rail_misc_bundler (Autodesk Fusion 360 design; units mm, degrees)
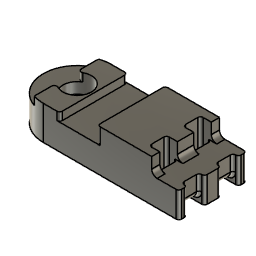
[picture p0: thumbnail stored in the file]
sketch "Sketch1" plane through (0, 0, 0) normal (0, 0, 1) x axis (1, 0, 0)
  line L1 (25, 6.25) -> (-6.25, 6.25)
  line L2 (25, -6.25) -> (25, 6.25)
  line L3 (-6.25, -6.25) -> (25, -6.25)
  line L4 (-6.25, 6.25) -> (-6.25, -6.25)
  line L5 (10, -6.25) -> (10, 6.25)
  line L6 (-2, -6.25) -> (-2, 6.25)
  line L7 (3, -6.25) -> (3, 6.25)
  line L8 (12, -6.25) -> (12, 6.25)
  line L9 (18, -4.75) -> (20, -4.75)
  line L10 (18, -1.5) -> (18, -4.75)
  line L11 (20, -1.5) -> (18, -1.5)
  line L12 (20, -4.75) -> (20, -1.5)
  line L13 (18, 1.5) -> (20, 1.5)
  line L14 (18, 4.75) -> (18, 1.5)
  line L15 (20, 4.75) -> (18, 4.75)
  line L16 (20, 1.5) -> (20, 4.75)
  line L17 (24, 4.75) -> (25, 4.75)
  line L18 (24, 1.5) -> (24, 4.75)
  line L19 (25, 1.5) -> (24, 1.5)
  line L20 (24, -1.5) -> (25, -1.5)
  line L21 (24, -4.75) -> (24, -1.5)
  line L22 (25, -4.75) -> (24, -4.75)
  line L23 (20, -1.5) -> (20, 1.5)
  line L24 (20, 6.25) -> (20, 4.75)
  line L25 (20, -6.25) -> (20, -4.75)
  line L26 (24, 4.75) -> (20, 4.75)
  line L27 (20, 1.5) -> (24, 1.5)
  line L28 (24, -1.5) -> (20, -1.5)
  line L29 (20, -4.75) -> (24, -4.75)
  circle C1 centre (0, 0) radius 2.625
  point P1 (0, 0)
  point P2 (0, 0)
  point P7 (10, 6.25)
  point P8 (10, -6.25)
  point P9 (-2, 6.25)
  point P10 (-2, -6.25)
  point P11 (3, 6.25)
  point P12 (3, -6.25)
  point P13 (12, 6.25)
  point P14 (12, -6.25)
  point P17 (18, -1.5)
  point P23 (25, 4.75)
  point P26 (25, 1.5)
  point P27 (25, -1.5)
  point P30 (25, -4.75)
  point P22 (20, 4.75)
  point P19 (20, 1.5)
  point P18 (20, -1.5)
  point P15 (20, -4.75)
  point P25 (24, 1.5)
  point P31 (20, 6.25)
  point P32 (20, -6.25)
  point P20 (18, 1.5)
  point P21 (18, 4.75)
  point P28 (24, -1.5)
  point P5 (25, -6.25)
  point P4 (25, 6.25)
  coincident P1 P2
  horizontal L1
  vertical L2
  horizontal L3
  vertical L4
  coincident L1 P7
  coincident L3 P8
  perpendicular L3 L5
  coincident L1 P9
  coincident L3 P10
  perpendicular L3 L6
  coincident L1 P11
  coincident L3 P12
  perpendicular L3 L7
  coincident L1 P13
  coincident L3 P14
  perpendicular L3 L8
  horizontal L9
  vertical L10
  horizontal L11
  vertical L12
  horizontal L13
  vertical L14
  horizontal L15
  vertical L16
  coincident P17 L14
  equal L11 L15
  equal L10 L14
  coincident L2 P23
  perpendicular L2 L17
  perpendicular L17 L18
  coincident L2 P26
  perpendicular L2 L19
  coincident L2 P27
  perpendicular L2 L20
  perpendicular L20 L21
  coincident L2 P30
  perpendicular L2 L22
  coincident P22 L17
  coincident P19 L19
  coincident P18 L20
  coincident P15 L22
  coincident P25 L21
  coincident L1 P31
  perpendicular L1 L24
  coincident L3 P32
  perpendicular L3 L25
  dimension "d1" diameter C1 = 5.25
  dimension "d2" distance P1 L4 = 6.25
  dimension "d3" distance P2 L1 = 6.25 (= "d2")
  dimension "d4" distance P1 L3 = 6.25 (= "d2")
  dimension "d5" distance P1 L5 = 10
  dimension "d6" distance P2 L7 = 3
  dimension "d7" distance P2 L6 = 2
  dimension "d8" distance P8 P14 = 2
  dimension "d9" distance P20 P21 = 3.25
  dimension "d10" distance P21 P22 = 2
  dimension "d11" distance P27 P28 = 1
  dimension "d12" distance L12 L21 = 4
  dimension "d13" distance P5 P8 = 15
  dimension "d14" distance P5 P30 = 1.5
  dimension "d15" distance P4 P23 = 1.5 (= "d14")
extrude "Extrude1" new body sketch "Sketch1" profile of C1 L1 L2 L3 L4 L5 L6 L7 L8 L9 L10 L11 L12 L13 L14 L15 L16 L17 L18 L19 L20 L21 L22 L23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 against normal blind 4.75
extrude "Extrude2" add sketch "Sketch1" profile of C1 L1 L3 L6 L7 along normal blind 1.5
extrude "Extrude3" add sketch "Sketch1" profile of L1 L3 L5 L8 L9 L10 L11 L13 L14 L15 L23 L24 L25 along normal blind 3
extrude "Extrude4" sketch "Sketch1" profile of L12 L16 L18 L21 L26 L27 L28 L29 blind 1
fillet "Fillet3" radius 0.5
fillet "Fillet4" radius 0.5
fillet "Fillet5" radius 6.25
chamfer "Chamfer1" distance 2.75
fillet "Fillet6" radius 1
fillet "Fillet7" radius 1
fillet "Fillet8" radius 0.5
fillet "Fillet9" radius 0.5
fillet "Fillet10" radius 0.5
fillet "Fillet1" radius 1.5
fillet "Fillet2" radius 1
named bodies: "bundler-misc"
